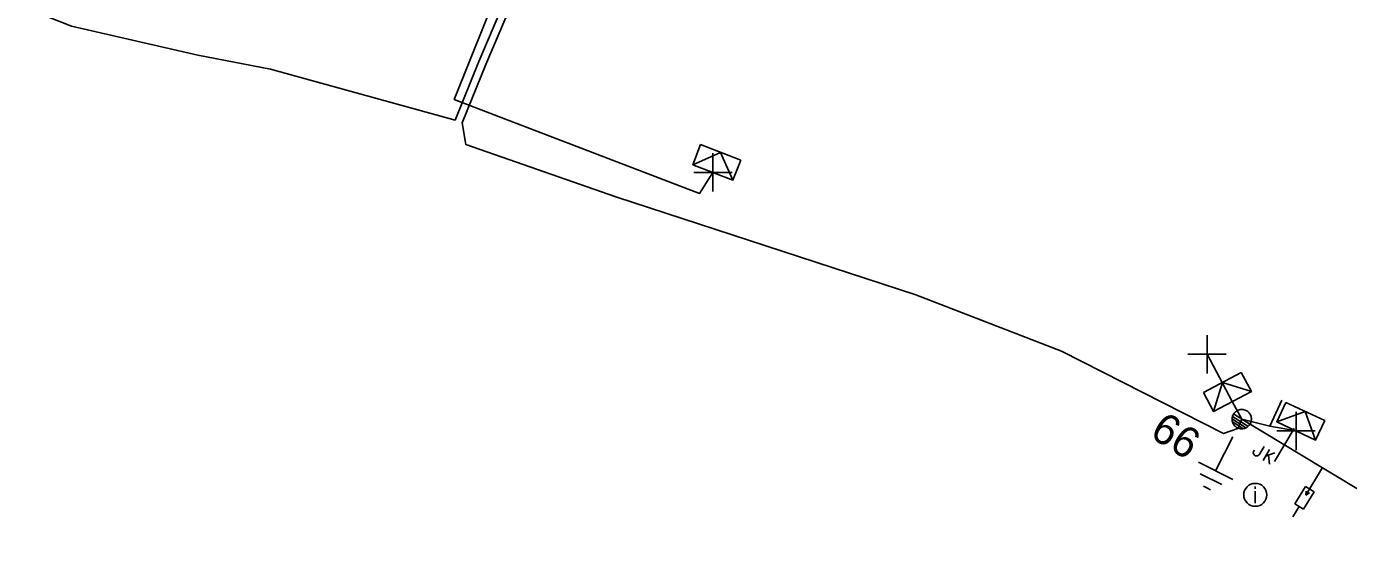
# Model space of a CAD drawing. Extents: x -540466 to -537383, y -1184038 to -1179972.
# Drawn here: x -537733.89 to -537690.78, y -1180542.13 to -1180525.39 of the extents above; entities that cross this region are included whole.
import ezdxf

# ---------------------------------------------------------------- set-up
doc = ezdxf.new("R2010")
doc.units = 0
for name, color, linetype in [('Vrstva 1', 7, 'Continuous'), ('Vrstva 10', 7, 'Continuous'), ('Vrstva 13', 7, 'Continuous'), ('Vrstva 14', 7, 'Continuous'), ('Vrstva 15', 7, 'Continuous'), ('Vrstva 16', 7, 'Continuous'), ('Vrstva 18', 7, 'Continuous'), ('Vrstva 2', 7, 'Continuous'), ('Vrstva 31', 7, 'Continuous'), ('Vrstva 34', 7, 'Continuous'), ('Vrstva 36', 7, 'Continuous'), ('Vrstva 5', 7, 'Continuous'), ('Vrstva 50', 7, 'Continuous'), ('Vrstva 52', 7, 'Continuous'), ('Vrstva 54', 7, 'Continuous'), ('Vrstva 59', 7, 'Continuous'), ('Vrstva 8', 7, 'Continuous'), ('Vrstva 9', 7, 'Continuous')]:
    doc.layers.add(name, color=color, linetype=linetype)

# ---------------------------------------------------------------- blocks, each defined once
blk = doc.blocks.new('NN440')
at = {"layer": 'Vrstva 2'}
for points in [[(0.631, -0.004), (0.627, 0.062), (0.617, 0.127), (0.6, 0.191), (0.577, 0.252), (0.547, 0.311), (0.511, 0.366), (0.469, 0.417), (0.423, 0.464), (0.371, 0.505), (0.316, 0.542), (0.257, 0.571), (0.196, 0.595), (0.132, 0.612), (0.067, 0.622), (0.001, 0.626), (-0.065, 0.622), (-0.13, 0.612), (-0.194, 0.595), (-0.255, 0.571), (-0.314, 0.542), (-0.369, 0.505), (-0.42, 0.464), (-0.467, 0.417), (-0.509, 0.366), (-0.544, 0.311), (-0.574, 0.252), (-0.598, 0.191), (-0.615, 0.127), (-0.626, 0.062), (-0.629, -0.004), (-0.626, -0.07), (-0.615, -0.135), (-0.598, -0.199), (-0.574, -0.26), (-0.544, -0.319), (-0.509, -0.374), (-0.467, -0.426), (-0.42, -0.472), (-0.369, -0.514), (-0.314, -0.55), (-0.255, -0.58), (-0.194, -0.603), (-0.13, -0.62), (-0.065, -0.631), (0.001, -0.634), (0.067, -0.631), (0.132, -0.62), (0.196, -0.603), (0.257, -0.58), (0.316, -0.55), (0.371, -0.514), (0.423, -0.472), (0.469, -0.426), (0.511, -0.374), (0.547, -0.319), (0.577, -0.26), (0.6, -0.199), (0.617, -0.135), (0.627, -0.07), (0.631, -0.004)], [(-0.631, 0), (0.629, 0)], [(-0.601, -0.177), (0.57, -0.177)], [(-0.513, -0.325), (0.501, -0.325)], [(-0.375, -0.473), (0.353, -0.473)]]:
    blk.add_lwpolyline(points, dxfattribs=at)
blk = doc.blocks.new('NN840')
at = {"layer": 'Vrstva 15'}
for points in [[(0.003, 0.619), (0.003, -0.631)], [(-0.538, -0.385), (-0.538, -0.71)], [(-0.332, -0.385), (-0.332, -0.798)], [(-0.332, -0.641), (-0.125, -0.385)], [(-0.745, -0.71), (-0.745, -0.66)], [(-0.73, -0.764), (-0.745, -0.71)], [(-0.657, -0.798), (-0.73, -0.764)], [(-0.627, -0.798), (-0.657, -0.798)], [(-0.558, -0.764), (-0.627, -0.798)], [(-0.538, -0.71), (-0.558, -0.764)], [(-0.263, -0.557), (-0.091, -0.798)]]:
    blk.add_lwpolyline(points, dxfattribs=at)
blk = doc.blocks.new('NN770')
at = {"layer": 'Vrstva 10'}
for p, q in [((0.002, 0.187), (0.002, 0.263)), ((0.002, -0.276), (0.002, 0.111))]:
    blk.add_line(p, q, dxfattribs=at)
blk.add_circle((0, -0.008), 0.375, dxfattribs=at)
blk = doc.blocks.new('NN800')
at = {"layer": 'Vrstva 1'}
for points in [[(-0.442, 0.442), (0.442, -0.442)], [(-0.442, -0.442), (0.442, 0.442)]]:
    blk.add_lwpolyline(points, dxfattribs=at)
blk = doc.blocks.new('NN820')
at = {"layer": 'Vrstva 13'}
for points in [[(-0.003, 0.004), (-0.003, -1.049)], [(-0.165, -0.813), (0.165, -0.813)], [(-0.165, -1.473), (-0.165, -0.813)], [(0.165, -0.813), (0.165, -1.473)], [(-0.003, -1.049), (-0.062, -0.926)], [(-0.003, -1.049), (0.057, -0.926)], [(0.165, -1.473), (-0.165, -1.473)], [(-0.003, -1.473), (-0.003, -1.871)]]:
    blk.add_lwpolyline(points, dxfattribs=at)
blk = doc.blocks.new('NN630')
at = {"layer": 'Vrstva 9'}
for points in [[(-0.003, -0.7), (-0.703, 0)], [(-0.703, -0.7), (-0.703, 0), (0.697, 0), (0.697, -0.7)], [(-0.003, -0.7), (0.697, 0)], [(-0.703, -0.7), (0.697, -0.7)]]:
    blk.add_lwpolyline(points, dxfattribs=at)
blk = doc.blocks.new('NN810')
at = {"layer": 'Vrstva 14'}
for points in [[(0.004, -0.64), (0.004, -1.89)], [(0.629, -1.89), (-0.621, -1.89)], [(0.388, -2.2), (-0.399, -2.2)], [(0.004, -2.515), (-0.124, -2.515)], [(0.137, -2.515), (0.004, -2.515)]]:
    blk.add_lwpolyline(points, dxfattribs=at)
blk = doc.blocks.new('NN510')
at = {"layer": 'Vrstva 2'}
blk.add_lwpolyline([(0.001, 0.002), (0.001, 0.939)], dxfattribs=at)

msp = doc.modelspace()

# ---------------------------------------------------------------- linework, layer by layer
at = {"layer": 'Vrstva 5'}
for points in [[(-537734.68, -1180524.19), (-537734.74, -1180524.45), (-537732.42, -1180525.38), (-537728.3, -1180526.32), (-537725.94, -1180526.78), (-537719.916, -1180528.443), (-537719.145, -1180526.532), (-537715.575, -1180518.142), (-537712.055, -1180509.59), (-537710.072, -1180505.214), (-537708.029, -1180501.425), (-537707.177, -1180501.531), (-537706.489, -1180502.117), (-537706.751, -1180502.897)], [(-537694.259, -1180538.2), (-537694.383, -1180538.509), (-537694.85, -1180538.67), (-537700.14, -1180535.98), (-537704.89, -1180534.15), (-537714.67, -1180530.95), (-537719.56, -1180529.24), (-537719.684, -1180528.537), (-537718.915, -1180526.628), (-537715.345, -1180518.238), (-537711.825, -1180509.69), (-537709.848, -1180505.326), (-537707.891, -1180501.695), (-537707.283, -1180501.769), (-537706.751, -1180502.223), (-537706.972, -1180502.847)]]:
    msp.add_lwpolyline(points, dxfattribs=at)
at = {"layer": 'Vrstva 50'}
msp.add_lwpolyline([(-537694.26, -1180538.199), (-537691.624, -1180539.786), (-537675.507, -1180549.486), (-537663.756, -1180552.682), (-537651.753, -1180559.088), (-537616.15, -1180576.16), (-537591.135, -1180593.384), (-537584.357, -1180598.332)], dxfattribs=at)
at = {"layer": 'Vrstva 52'}
msp.add_lwpolyline([(-537706.972, -1180502.847), (-537709.876, -1180502.687), (-537719.944, -1180527.767), (-537711.939, -1180530.834), (-537711.509, -1180530.148)], dxfattribs=at)
at = {"layer": 'Vrstva 54'}
msp.add_lwpolyline([(-537694.26, -1180538.2), (-537693.348, -1180538.435), (-537692.489, -1180538.584)], dxfattribs=at)
at = {"layer": 'Vrstva 59'}
msp.add_lwpolyline([(-537694.568, -1180537.623), (-537695.392, -1180536.085)], dxfattribs=at)
at = {"layer": 'Vrstva 8'}
msp.add_lwpolyline([(-537694.26, -1180538.2), (-537694.568, -1180537.623)], dxfattribs=at)

# ---------------------------------------------------------------- block references
at = {"layer": 'Vrstva 13', "xscale": 0.5, "yscale": 0.5, "rotation": -32.04825282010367}
msp.add_blockref('NN440', (-537694.26, -1180538.199), dxfattribs=at)
at = {"layer": 'Vrstva 13', "rotation": -25.18302502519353}
msp.add_blockref('NN510', (-537693.349, -1180538.436), dxfattribs=at)
at = {"layer": 'Vrstva 15', "rotation": -26.91949160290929}
msp.add_blockref('NN810', (-537694.261, -1180538.2), dxfattribs=at)
at = {"layer": 'Vrstva 16', "rotation": -31.042769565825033}
msp.add_blockref('NN820', (-537691.624, -1180539.786), dxfattribs=at)
at = {"layer": 'Vrstva 18', "rotation": -31.049908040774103}
msp.add_blockref('NN840', (-537692.87, -1180539.036), dxfattribs=at)
at = {"layer": 'Vrstva 31'}
for p, rotation in [((-537711.509, -1180530.148), 158.978883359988), ((-537694.568, -1180537.623), -152.1244896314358), ((-537692.489, -1180538.584), 154.81697500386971)]:
    msp.add_blockref('NN630', p, dxfattribs=dict(at, rotation=rotation))
at = {"layer": 'Vrstva 34'}
for p, rotation in [((-537711.509, -1180530.148), 45), ((-537695.392, -1180536.085), 45), ((-537692.489, -1180538.584), 44.99999995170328)]:
    msp.add_blockref('NN800', p, dxfattribs=dict(at, rotation=rotation))
at = {"layer": 'Vrstva 36'}
msp.add_blockref('NN770', (-537693.82, -1180540.662), dxfattribs=at)

# ---------------------------------------------------------------- texts
at = {"layer": 'Vrstva 14'}
msp.add_text('66', height=1, rotation=327.884, dxfattribs=at).set_placement((-537697.298, -1180538.761))

doc.saveas('drawing.dxf')
